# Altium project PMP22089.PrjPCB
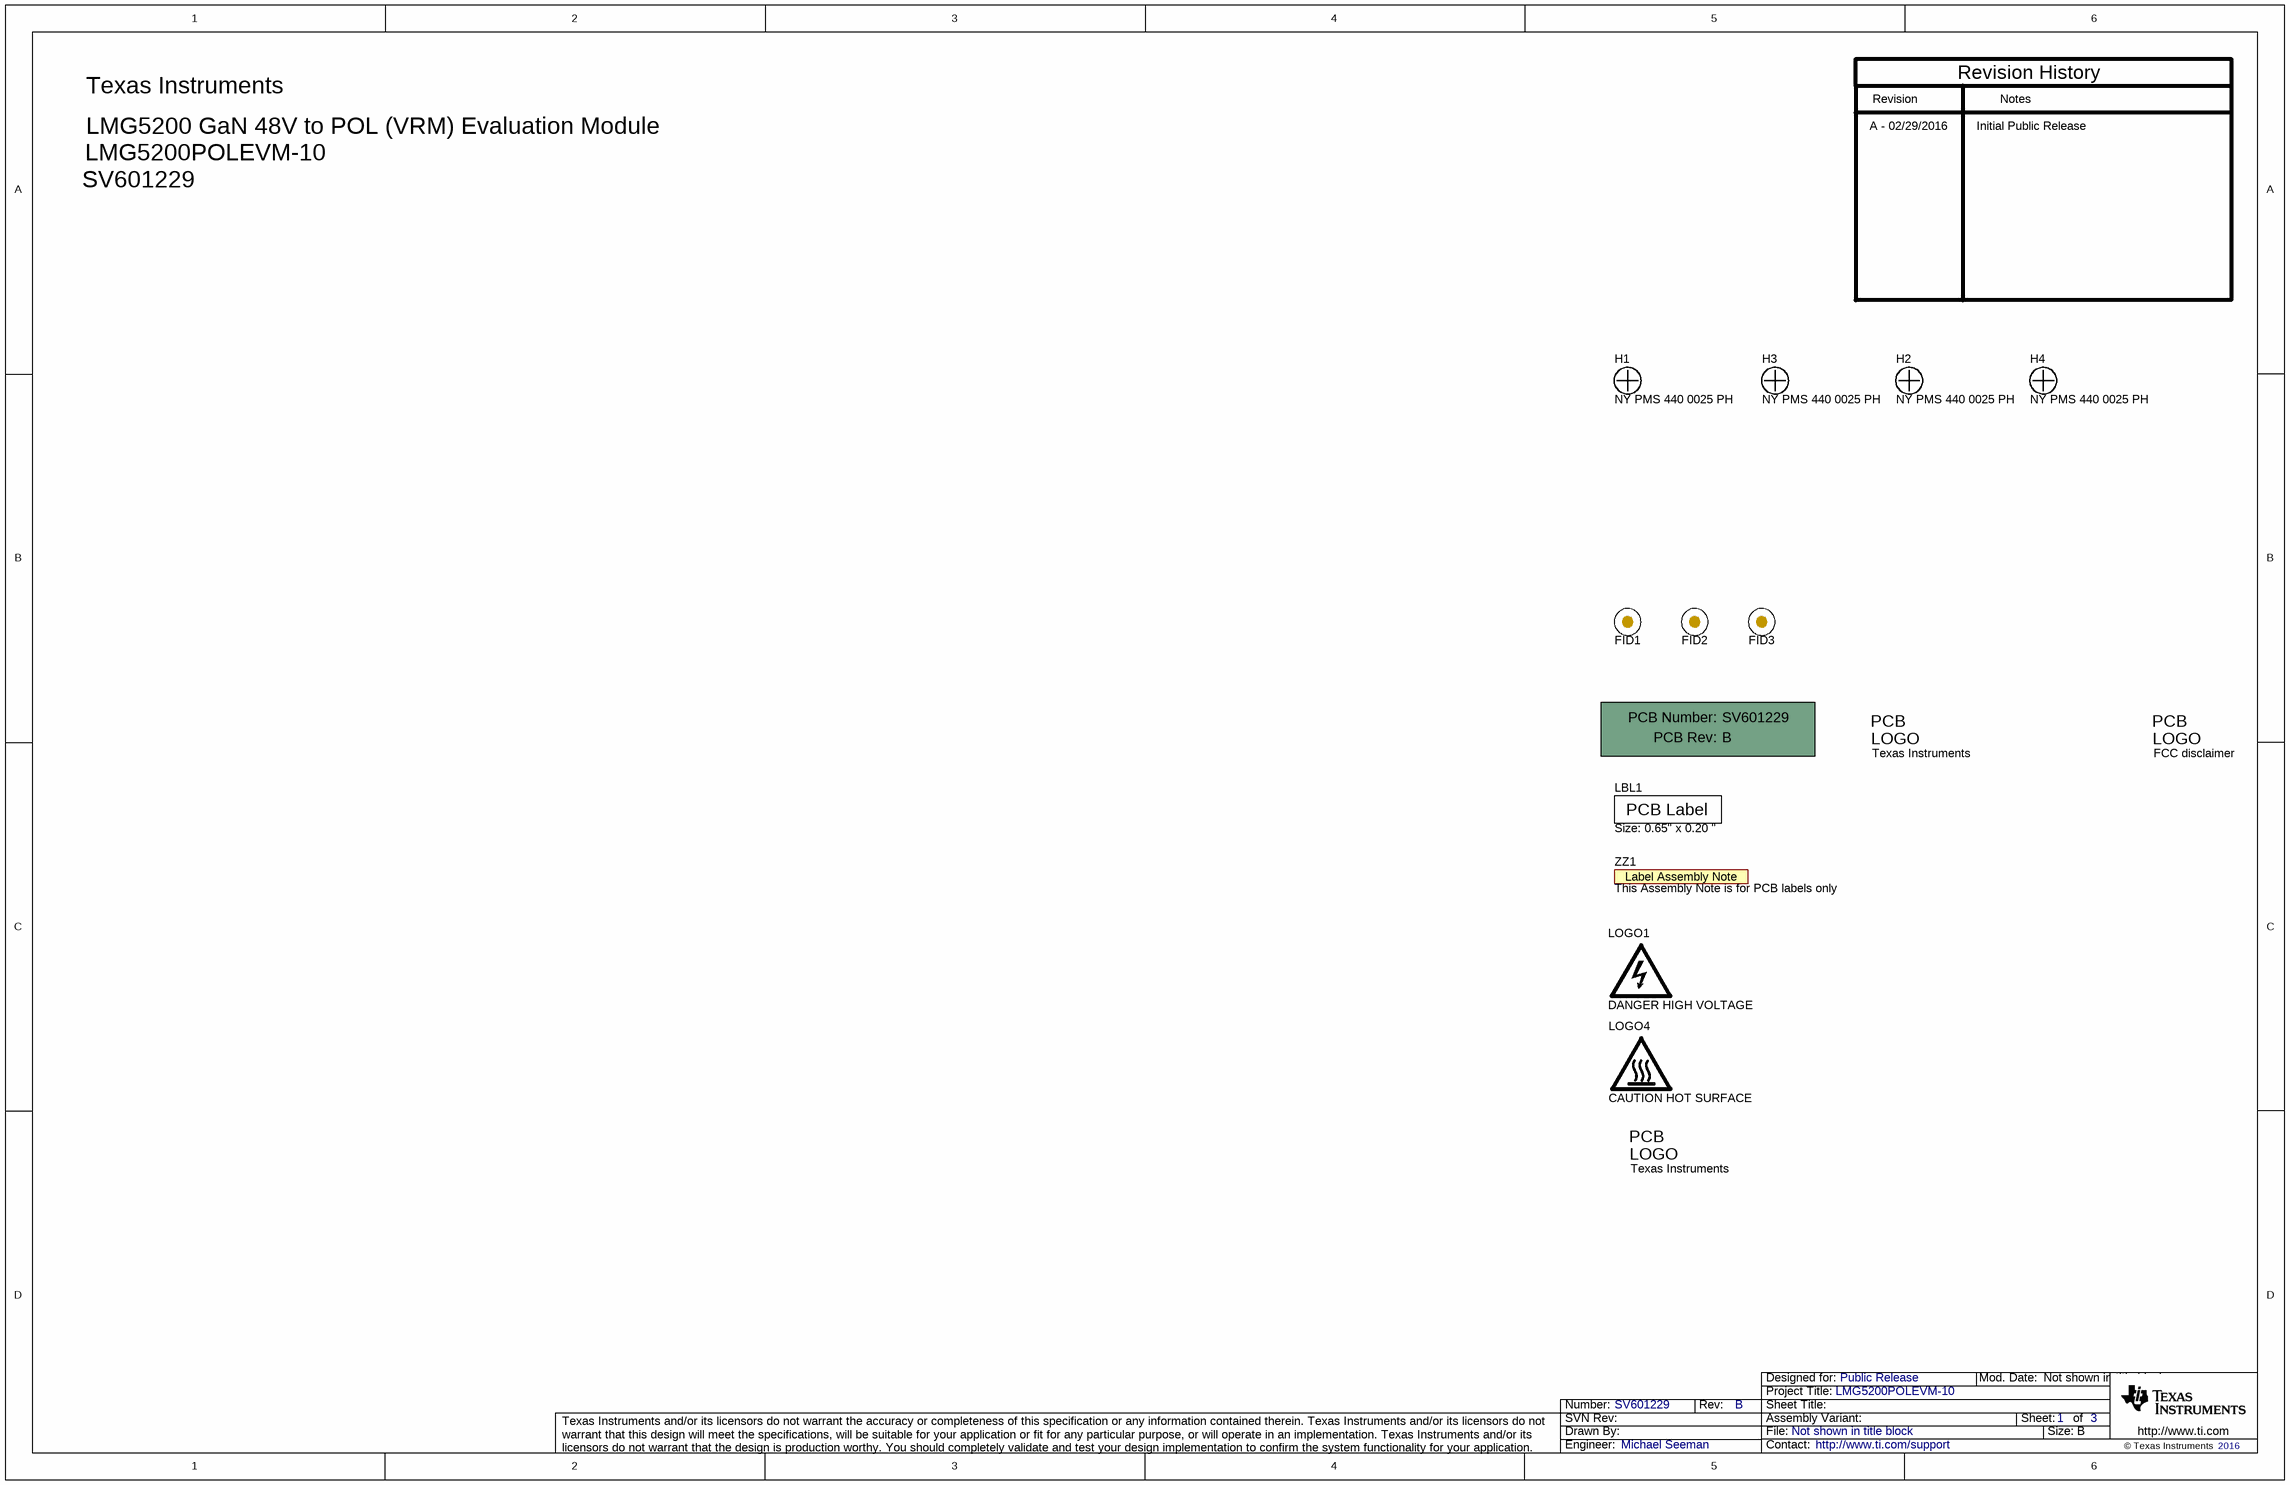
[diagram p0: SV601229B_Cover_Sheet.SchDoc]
CopyrightYear: 2016; PCB_Layout: a0220741; PCB_Rev: B; PRJ_Customer: Public Release; PRJ_Engineer: Michael Seeman; PRJ_Number: SV601229; PRJ_Title: LMG5200POLEVM-10; SCH_Rev: B; TechSupport: http://www.ti.com/support
3 sheets, 188 parts. Net scope: flat (ports and power ports of the same name join across sheets).
Board file: SV601229B_PCB.PcbDoc
Sheets:
  SV601229B_Cover_Sheet.SchDoc
  SV601229B_Controller.SchDoc
  SV601229B_Power_Stage.SchDoc

## Sheet SV601229B_Cover_Sheet.SchDoc
size 431 x 279 mm; Date: Not shown in title block; ApprovedBy: Not shown in title block; CheckedBy: Not shown in title block; Author: Not shown in title block; CompanyName: Not shown in title block; Engineer: Not shown in title block; Organization: Not shown in title block; Address1: Not shown in title block; Address2: Not shown in title block; Address3: Not shown in title block; Address4: Not shown in title block; DocumentNumber: 1; Revision: Use project parameter SCH_Rev; SheetNumber: 1; SheetTotal: 3; PageSetup: Record=PageOptions¦CenterHorizontal=True¦CenterVertical=True¦PrintScale=1.00¦XCorrection=1.00¦YCorrection=1.00¦PrintKind=0¦BorderSize=5000000¦LeftOffset=0¦BottomOffset=0¦Orientation=2¦PaperLength=1000¦PaperWidth=1000¦Scale=100¦PaperSource=15¦PrintQuality=600¦MediaType=1¦DitherType=10¦PaperKind=Letter¦PrintScaleMode=1

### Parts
!PCB1  Printed Circuit Board  (value not drawn)  (mechanical)
FID1  Fiducial  [Fiducial10-20]  (value not drawn)  (mechanical)
FID2  Fiducial  [Fiducial10-20]  (value not drawn)  (mechanical)
FID3  Fiducial  [Fiducial10-20]  (value not drawn)  (mechanical)
H1  NY PMS 440 0025 PH  [NY PMS 440 0025 PH]
H2  NY PMS 440 0025 PH  [NY PMS 440 0025 PH]
H3  NY PMS 440 0025 PH  [NY PMS 440 0025 PH]
H4  NY PMS 440 0025 PH  [NY PMS 440 0025 PH]
LBL1  Size: 0.65" x 0.20 "  [Label_650x200]
LOGO1  DANGER HIGH VOLTAGE  [IEC_HighVoltage_Small]  (no BOM)
Logo2  Texas Instruments  [TI_Stacked_Overlay_Small]  (no BOM)
Logo3  FCC disclaimer  [FCC_disclaimer]  (no BOM)
LOGO4  CAUTION HOT SURFACE  [IEC_HotSurface_Small]  (no BOM)
Logo6  Texas Instruments  [TI_Symbol_Overlay_Small]  (no BOM)
ZZ1  This Assembly Note is for PCB labels only  [AssemblyNoteLabel]  (no BOM)

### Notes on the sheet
- Texas Instruments
- Revision
- Notes
- Revision History
- LMG5200 GaN 48V to POL (VRM) Evaluation Module
- LMG5200POLEVM-10
- A - 02/29/2016
- Initial Public Release
- SV601229

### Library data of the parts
!PCB1 = PCB: Manufacturer: Any; PartNumber: SV601229; SymbolCreator: a0412235
FID1-FID3 = Fiducial: Fiducial mark.  There is nothing to buy or mount.; SymbolCreator: codlsc
H1-H4 = NY PMS 440 0025 PH: Machine Screw, Round, #4-40 x 1/4, Nylon, Philips panhead; Manufacturer: B&F Fastener Supply; CompType: Hardware; SymbolCreator: codlsc; U/M: EA
LBL1 = THT-14-423-10: Thermal Transfer Printable Labels, 0.650" W x 0.200" H - 10,000 per roll; Manufacturer: Brady; SymbolCreator: a0412235; CompType: Label
LOGO1 = IEC_HighVoltage: IEC 61010-1 High Voltage Warning; SymbolCreator: a0412235
Logo2 Logo6 = TI_Logo: Texas Instrument Corporate Signature; SymbolCreator: a0412235
Logo3 = FCC_disclaimer: SymbolCreator: codlsc
LOGO4 = IEC_HotSurface: IEC 61010-1 Hot Surface Warning; SymbolCreator: a0412235
ZZ1 = AssemblyNoteLabel: SymbolCreator: a0412235

## Sheet SV601229B_Controller.SchDoc
size 431 x 279 mm; Date: Not shown in title block; ApprovedBy: Not shown in title block; CheckedBy: Not shown in title block; Author: Not shown in title block; CompanyName: Not shown in title block; Engineer: Not shown in title block; Organization: Not shown in title block; Address1: Not shown in title block; Address2: Not shown in title block; Address3: Not shown in title block; Address4: Not shown in title block; DocumentNumber: 3; Revision: Use project parameter SCH_Rev; SheetNumber: 3; SheetTotal: 3; PageSetup: Record=PageOptions¦CenterHorizontal=True¦CenterVertical=True¦PrintScale=1.00¦XCorrection=1.00¦YCorrection=1.00¦PrintKind=0¦BorderSize=5000000¦LeftOffset=0¦BottomOffset=0¦Orientation=2¦PaperLength=1000¦PaperWidth=1000¦Scale=100¦PaperSource=15¦PrintQuality=600¦MediaType=1¦DitherType=10¦PaperKind=Letter¦PrintScaleMode=1
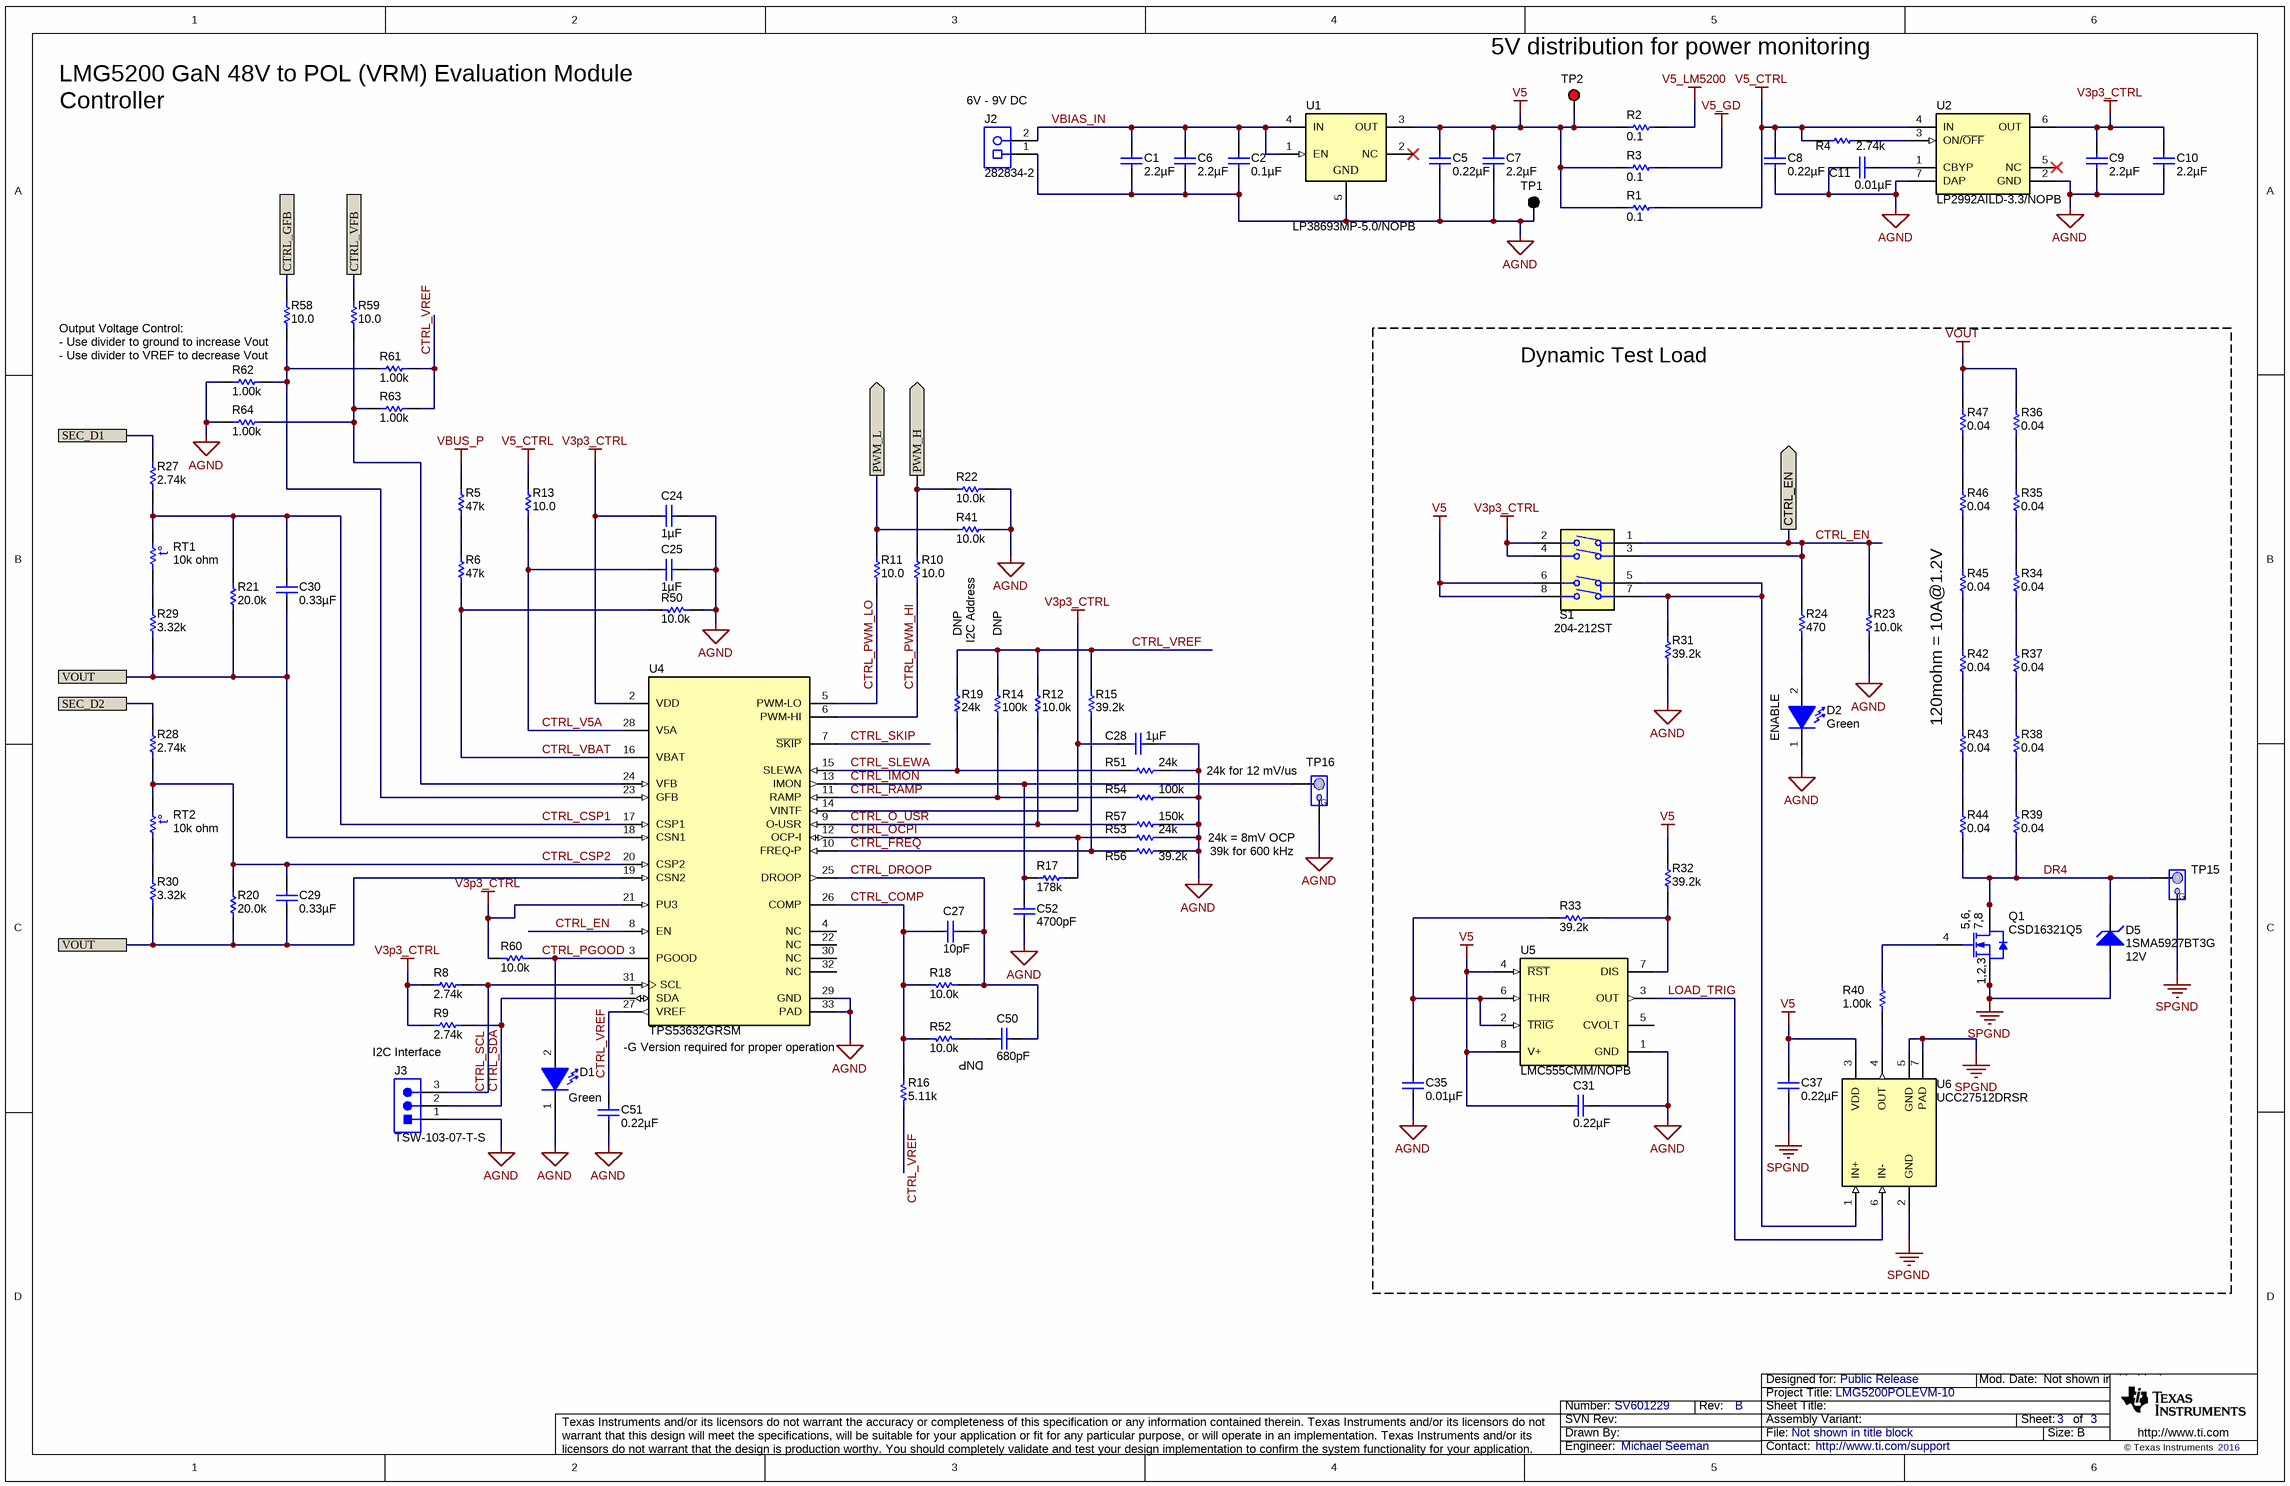
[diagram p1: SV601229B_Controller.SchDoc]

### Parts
C1  ValueDisplayed: 2.2µF  [0805]  (hidden comment: C0805C225K4RACTU)
C2  ValueDisplayed: 0.1µF  [0402]  (hidden comment: C1005X7R1H104K050BB)
C5  ValueDisplayed: 0.22µF  [0402]  (hidden comment: C1005X7R1C224K050BC)
C6  ValueDisplayed: 2.2µF  [0805]  (hidden comment: C0805C225K4RACTU)
C7  ValueDisplayed: 2.2µF  [0805]  (hidden comment: C0805C225K4RACTU)
C8  ValueDisplayed: 0.22µF  [0402]  (hidden comment: C1005X7R1C224K050BC)
C9  ValueDisplayed: 2.2µF  [0805]  (hidden comment: C0805C225K4RACTU)
C10  ValueDisplayed: 2.2µF  [0805]  (hidden comment: C0805C225K4RACTU)
C11  ValueDisplayed: 0.01µF  [0402]  (hidden comment: C1005X7R1C103K050BA)
C24  ValueDisplayed: 1µF  [0402]  (hidden comment: GRM155R61A105KE15D)
C25  ValueDisplayed: 1µF  [0402]  (hidden comment: GRM155R61A105KE15D)
C27  ValueDisplayed: 10pF  [0402]  (hidden comment: GRM1555C1H100JA01D)
C28  ValueDisplayed: 1µF  [0402]  (hidden comment: GRM155R61A105KE15D)
C29  ValueDisplayed: 0.33µF  [0603]  (hidden comment: GRM188R71C334KA01D)
C30  ValueDisplayed: 0.33µF  [0603]  (hidden comment: GRM188R71C334KA01D)
C31  ValueDisplayed: 0.22µF  [0603]  (hidden comment: C0603C224K4RACTU)
C35  ValueDisplayed: 0.01µF  [0402]  (hidden comment: C1005X7R1C103K050BA)
C37  ValueDisplayed: 0.22µF  [0603]  (hidden comment: C0603C224K4RACTU)
C50  ValueDisplayed: 680pF  [0402]  (hidden comment: GRM1555C1E681JA01D)
C51  ValueDisplayed: 0.22µF  [0402]  (hidden comment: C1005X7R1C224K050BC)
C52  ValueDisplayed: 4700pF  [0402]  (hidden comment: GRM155R71C472KA01D)
D1  value Green  [WL-SMCW_GREEN]  (hidden comment: 150060GS75000)
D2  value Green  [WL-SMCW_GREEN]  (hidden comment: 150060GS75000)
D5  1SMA5927BT3G  value 12V  [SMA]
J2  282834-2  [TEC_282834-2]
J3  TSW-103-07-T-S  [Samtec_TSW-103-07-T-S]
Q1  CSD16321Q5  [TRANS_NexFET_Q5]
R1  ValueDisplayed: 0.1  [0402]  (hidden comment: ERJ-2BSFR10X)
R2  ValueDisplayed: 0.1  [0402]  (hidden comment: ERJ-2BSFR10X)
R3  ValueDisplayed: 0.1  [0402]  (hidden comment: ERJ-2BSFR10X)
R4  ValueDisplayed: 2.74k  [0402]  (hidden comment: CRCW04022K74FKED)
R5  ValueDisplayed: 47k  [0402]  (hidden comment: CRCW040247K0JNED)
R6  ValueDisplayed: 47k  [0402]  (hidden comment: CRCW040247K0JNED)
R8  ValueDisplayed: 2.74k  [0402]  (hidden comment: CRCW04022K74FKED)
R9  ValueDisplayed: 2.74k  [0402]  (hidden comment: CRCW04022K74FKED)
R10  ValueDisplayed: 10.0  [0402]  (hidden comment: CRCW040210R0FKED)
R11  ValueDisplayed: 10.0  [0402]  (hidden comment: CRCW040210R0FKED)
R12  ValueDisplayed: 10.0k  [0402]  (hidden comment: CRCW040210K0FKED)
R13  ValueDisplayed: 10.0  [0402]  (hidden comment: CRCW040210R0FKED)
R14  ValueDisplayed: 100k  [0402]  (hidden comment: CRCW0402100KFKED)
R15  ValueDisplayed: 39.2k  [0402]  (hidden comment: CRCW040239K2FKED)
R16  ValueDisplayed: 5.11k  [0402]  (hidden comment: CRCW04025K11FKED)
R17  ValueDisplayed: 178k  [0402]  (hidden comment: CRCW0402178KFKED)
R18  ValueDisplayed: 10.0k  [0402]  (hidden comment: CRCW040210K0FKED)
R19  ValueDisplayed: 24k  [0402]  (hidden comment: CRCW040224K0JNED)
R20  ValueDisplayed: 20.0k  [0402]  (hidden comment: CRCW040220K0FKED)
R21  ValueDisplayed: 20.0k  [0402]  (hidden comment: CRCW040220K0FKED)
R22  ValueDisplayed: 10.0k  [0402]  (hidden comment: CRCW040210K0FKED)
R23  ValueDisplayed: 10.0k  [0402]  (hidden comment: CRCW040210K0FKED)
R24  ValueDisplayed: 470  [0402]  (hidden comment: CRCW0402470RJNED)
R27  ValueDisplayed: 2.74k  [0402]  (hidden comment: CRCW04022K74FKED)
R28  ValueDisplayed: 2.74k  [0402]  (hidden comment: CRCW04022K74FKED)
R29  ValueDisplayed: 3.32k  [0402]  (hidden comment: CRCW04023K32FKED)
R30  ValueDisplayed: 3.32k  [0402]  (hidden comment: CRCW04023K32FKED)
R31  ValueDisplayed: 39.2k  [0402]  (hidden comment: CRCW040239K2FKED)
R32  ValueDisplayed: 39.2k  [0402]  (hidden comment: CRCW040239K2FKED)
R33  ValueDisplayed: 39.2k  [0402]  (hidden comment: CRCW040239K2FKED)
R34  ValueDisplayed: 0.04  [2512]  (hidden comment: CRA2512-FZ-R040ELF)
R35  ValueDisplayed: 0.04  [2512]  (hidden comment: CRA2512-FZ-R040ELF)
R36  ValueDisplayed: 0.04  [2512]  (hidden comment: CRA2512-FZ-R040ELF)
R37  ValueDisplayed: 0.04  [2512]  (hidden comment: CRA2512-FZ-R040ELF)
R38  ValueDisplayed: 0.04  [2512]  (hidden comment: CRA2512-FZ-R040ELF)
R39  ValueDisplayed: 0.04  [2512]  (hidden comment: CRA2512-FZ-R040ELF)
R40  ValueDisplayed: 1.00k  [0402]  (hidden comment: CRCW04021K00FKED)
R41  ValueDisplayed: 10.0k  [0402]  (hidden comment: CRCW040210K0FKED)
R42  ValueDisplayed: 0.04  [2512]  (hidden comment: CRA2512-FZ-R040ELF)
R43  ValueDisplayed: 0.04  [2512]  (hidden comment: CRA2512-FZ-R040ELF)
R44  ValueDisplayed: 0.04  [2512]  (hidden comment: CRA2512-FZ-R040ELF)
R45  ValueDisplayed: 0.04  [2512]  (hidden comment: CRA2512-FZ-R040ELF)
R46  ValueDisplayed: 0.04  [2512]  (hidden comment: CRA2512-FZ-R040ELF)
R47  ValueDisplayed: 0.04  [2512]  (hidden comment: CRA2512-FZ-R040ELF)
R50  ValueDisplayed: 10.0k  [0402]  (hidden comment: CRCW040210K0FKED)
R51  ValueDisplayed: 24k  [0402]  (hidden comment: CRCW040224K0JNED)
R52  ValueDisplayed: 10.0k  [0402]  (hidden comment: CRCW040210K0FKED)
R53  ValueDisplayed: 24k  [0402]  (hidden comment: CRCW040224K0JNED)
R54  ValueDisplayed: 100k  [0402]  (hidden comment: CRCW0402100KFKED)
R56  ValueDisplayed: 39.2k  [0402]  (hidden comment: CRCW040239K2FKED)
R57  ValueDisplayed: 150k  [0603]  (hidden comment: CRCW0603150KFKEA)
R58  ValueDisplayed: 10.0  [0402]  (hidden comment: CRCW040210R0FKED)
R59  ValueDisplayed: 10.0  [0402]  (hidden comment: CRCW040210R0FKED)
R60  ValueDisplayed: 10.0k  [0402]  (hidden comment: CRCW040210K0FKED)
R61  ValueDisplayed: 1.00k  [0402]  (hidden comment: CRCW04021K00FKED)
R62  ValueDisplayed: 1.00k  [0402]  (hidden comment: CRCW04021K00FKED)
R63  ValueDisplayed: 1.00k  [0402]  (hidden comment: CRCW04021K00FKED)
R64  ValueDisplayed: 1.00k  [0402]  (hidden comment: CRCW04021K00FKED)
RT1  value 10k ohm  [0402]  (hidden comment: NCP15XH103J03RC)
RT2  value 10k ohm  [0402]  (hidden comment: NCP15XH103J03RC)
S1  204-212ST  [SW_204-212]
TP1  5011  [Keystone5011]  (value not drawn)
TP2  5010  [Keystone5010]  (value not drawn)
TP15  TP_PIGTAIL  [TP_PIGTAIL]  (value not drawn)  (no BOM)
TP16  TP_PIGTAIL  [TP_PIGTAIL]  (value not drawn)  (no BOM)
U1  LP38693MP-5.0/NOPB  [MP05A_N]
U2  LP2992AILD-3.3/NOPB  [LDE06A]
U4  TPS53632GRSM  [RSM0032B_NV]
U5  LMC555CMM/NOPB  [MUA08A_N]
U6  UCC27512DRSR  [DRS0006A]

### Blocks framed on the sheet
Dynamic Test Load: C31 C35 C37 D2 D5 Q1 R23 R24 R31-R40 R42-R47 S1 TP15 U5 U6

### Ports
CTRL_EN (out), CTRL_GFB, CTRL_VFB, PWM_H (out), PWM_L (out), SEC_D1, SEC_D2, VOUT

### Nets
AGND: C1.2 C2.2 C5.1 C6.2 C7.2 C8.1 C9.2 C10.2 C11.2 C24.1 C25.2 C28.1 C31.2 C35.2 C51.2 C52.1 D1.1(K) D2.1(K) J2.1 J3.1 R22.2 R23.1 R31.1 R41.2 R50.2 R51.2 R53.2 R54.2 R56.2 R57.1 R62.2 R64.2 TP1.1 TP16.2 U1.5(GND) U2.2(GND) U2.7(DAP) U4.29(GND) U4.33(PAD) U5.1(GND)
SPGND: C37.2 D5.2(A) Q1.1(S) Q1.2(S) Q1.3(S) TP15.2 U6.2(GND) U6.5(GND) U6.7(PAD)
V3p3_CTRL: C9.1 C10.1 C24.2 C28.2 R8.2 R9.2 R60.2 S1.2 S1.4 U2.6(OUT) U4.2(VDD) U4.14(VINTF) U4.21(PU3)
V5: C5.2 C7.1 C31.1 C37.1 R1.1 R2.1 R3.1 R32.1 S1.6 S1.8 TP2.1 U1.3(OUT) U5.4(~{RST}) U5.8(V+) U6.3(VDD)
V5_CTRL: C8.2 R1.2 R4.2 R13.2 U2.4(IN)
V5_GD: R3.2
V5_LM5200: R2.2
VBUS_P: R5.2
VOUT: C29.2 C30.2 R20.1 R21.1 R29.1 R30.1 R36.2 R47.2 U4.18(CSN1) U4.19(CSN2) ; port VOUT
CTRL_COMP: C27.1 R16.1 R18.2 R52.2 U4.26(COMP)
CTRL_CSP1: C30.1 R21.2 R27.1 RT1.2 U4.17(CSP1)
CTRL_CSP2: C29.1 R20.2 R28.1 RT2.2 U4.20(CSP2)
CTRL_DROOP: C27.2 C50.2 R18.1 U4.25(DROOP)
CTRL_EN: R23.2 R24.2 S1.1 S1.3 U4.8(EN) ; port CTRL_EN
CTRL_FREQ: R15.1 R56.1 U4.10(FREQ-P)
CTRL_GFB: R58.2 ; port CTRL_GFB
CTRL_IMON: C52.2 R17.2 TP16.1 U4.13(IMON)
CTRL_O_USR: R12.2 R57.2 U4.9(O-USR)
CTRL_OCPI: R17.1 R53.1 U4.12(OCP-I)
CTRL_PGOOD: D1.2(A) R60.1 U4.3(PGOOD)
CTRL_PWM_HI: R10.2 U4.6(PWM-HI)
CTRL_PWM_LO: R11.2 U4.5(PWM-LO)
CTRL_RAMP: R14.2 R54.1 U4.11(RAMP)
CTRL_SCL: J3.3 R8.1 U4.31(SCL)
CTRL_SDA: J3.2 R9.1 U4.1(SDA)
CTRL_SKIP: U4.7(~{SKIP})
CTRL_SLEWA: R19.1 R51.1 U4.15(SLEWA)
CTRL_V5A: C25.1 R13.1 U4.28(V5A)
CTRL_VBAT: R6.1 R50.1 U4.16(VBAT)
CTRL_VFB: R59.2 ; port CTRL_VFB
CTRL_VREF: C51.1 R12.1 R14.1 R15.2 R16.2 R19.2 R61.1 R63.1 U4.27(VREF)
DR4: D5.1(K) Q1.5(D) Q1.6(D) Q1.7(D) Q1.8(D) Q1.9(D) R39.1 R44.1 TP15.1
LOAD_TRIG: U5.3(OUT) U6.6(IN-)
PWM_H: R10.1 R22.1 ; port PWM_H
PWM_L: R11.1 R41.1 ; port PWM_L
SEC_D1: R27.2 ; port SEC_D1
SEC_D2: R28.2 ; port SEC_D2
VBIAS_IN: C1.1 C2.1 C6.1 J2.2 U1.1(EN) U1.4(IN)
NetC11_1: C11.1 U2.1(CBYP)
NetC35_1: C35.1 R33.1 U5.2(~{TRIG}) U5.6(THR)
NetC50_1: C50.1 R52.1
NetD2_2: D2.2(A) R24.1
NetQ1_4: Q1.4(G) R40.2
NetR4_1: R4.1 U2.3(ON/~{OFF})
NetR5_1: R5.1 R6.2
NetR29_2: R29.2 RT1.1
NetR30_2: R30.2 RT2.1
NetR31_2: R31.2 S1.5 S1.7 U6.1(IN+)
NetR32_2: R32.2 R33.2 U5.7(DIS)
NetR34_1: R34.1 R37.2
NetR34_2: R34.2 R35.1
NetR35_2: R35.2 R36.1
NetR37_1: R37.1 R38.2
NetR38_1: R38.1 R39.2
NetR40_1: R40.1 U6.4(OUT)
NetR42_1: R42.1 R43.2
NetR42_2: R42.2 R45.1
NetR43_1: R43.1 R44.2
NetR45_2: R45.2 R46.1
NetR46_2: R46.2 R47.1
NetR58_1: R58.1 R61.2 R62.1 U4.23(GFB)
NetR59_1: R59.1 R63.2 R64.1 U4.24(VFB)

Not connected (* = marked no-connect by the designer): U1 2(NC)*; U2 5(NC)*; U4 4(NC) 22(NC) 30(NC) 32(NC); U5 5(CVOLT)

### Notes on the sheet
- LMG5200 GaN 48V to POL (VRM) Evaluation Module
- Controller
- (near J2) 6V - 9V DC
- (near TP2) 5V distribution for power monitoring
- Output Voltage Control:
- (near R58) - Use divider to ground to increase Vout
- - Use divider to VREF to decrease Vout
- DNP
- I2C Address
- 120mohm = 10A@1.2V
- (near TP16) 24k for 12 mV/us
- (near D2) ENABLE
- (near TP16) 24k = 8mV OCP
- 39k for 600 kHz
- (near U4) -G Version required for proper operation
- I2C Interface

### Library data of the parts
C1 C6 C7 C9 C10 = C0805C225K4RACTU: CAP, CERM, 2.2 µF, 16 V, +/- 10%, X7R, 0805; Manufacturer: Kemet; Polarized: N; CompType: Capacitor; Value: 2.2uF; U/M: EA; Cap_F: 0.0000022; Tolerance_%: 10; ESR_ohm: 0.008; Value1: 0.008 ohm; VDC_V: 16; Value2: 16V; IRMS_A: 15.55; TaMin_C: -55; TaMax_C: 125
C2 = C1005X7R1H104K050BB: CAP, CERM, 0.1 µF, 50 V, +/- 10%, X7R, 0402; Manufacturer: TDK; Polarized: N; CompType: Capacitor; Value: 0.1uF; U/M: EA; Cap_F: 0.0000001; Tolerance_%: 10; ESR_ohm: 0.039064; Value1: 0.039064 ohm; VDC_V: 50; Value2: 50V; IRMS_A: 0.814669; TaMin_C: -55; TaMax_C: 125; AEC Category: Q200
C5 C8 C51 = C1005X7R1C224K050BC: CAP, CERM, 0.22 µF, 16 V, +/- 10%, X7R, 0402; Manufacturer: TDK; Polarized: N; CompType: Capacitor; Value: 0.22uF; U/M: EA; Cap_F: 0.00000022; Tolerance_%: 10; Value1: Unknown; VDC_V: 16; Value2: 16V; TaMin_C: -55; TaMax_C: 125
C11 C35 = C1005X7R1C103K050BA: CAP, CERM, 0.01 µF, 16 V, +/- 10%, X7R, 0402; Manufacturer: TDK; Polarized: N; CompType: Capacitor; Value: 0.01uF; U/M: EA; Cap_F: 0.00000001; Tolerance_%: 10; ESR_ohm: 0.0623; Value1: 0.0623 ohm; VDC_V: 16; Value2: 16V; TaMin_C: -55; TaMax_C: 125; AEC Category: Q200
C24 C25 C28 = GRM155R61A105KE15D: CAP, CERM, 1uF, 10V, +/-10%, X5R, 0402; Manufacturer: MuRata; Polarized: N; CompType: Capacitor; U/M: EA; Cap_F: 0.000001; Tolerance_%: 10; Value1: Unknown; TaMin_C: -55; TaMax_C: 85
C27 = GRM1555C1H100JA01D: CAP, CERM, 10 pF, 50 V, +/- 5%, C0G/NP0, 0402; Manufacturer: MuRata; Polarized: N; CompType: Capacitor; Value: 10pF; U/M: EA; Cap_F: 0.00000000001; Tolerance_%: 5; Value1: Unknown; VDC_V: 50; Value2: 50V; TaMin_C: -55; TaMax_C: 125
C29 C30 = GRM188R71C334KA01D: CAP, CERM, 0.33 µF, 16 V, +/- 10%, X7R, 0603; Manufacturer: MuRata; Polarized: N; CompType: Capacitor; Value: 0.33uF; U/M: EA; Cap_F: 0.00000033; Tolerance_%: 10; Value1: Unknown; VDC_V: 16; Value2: 16V; TaMin_C: -55; TaMax_C: 125
C31 C37 = C0603C224K4RACTU: CAP, CERM, 0.22 µF, 16 V, +/- 10%, X7R, 0603; Manufacturer: Kemet; Polarized: N; CompType: Capacitor; Value: 0.22uF; U/M: EA; Cap_F: 0.00000022; Tolerance_%: 10; Value1: Unknown; VDC_V: 16; Value2: 16V; TaMin_C: -55; TaMax_C: 125
C50 = GRM1555C1E681JA01D: CAP, CERM, 680 pF, 25 V, +/- 5%, C0G/NP0, 0402; Manufacturer: MuRata; Polarized: N; CompType: Capacitor; Value: 680pF; U/M: EA; Cap_F: 0.00000000068; Tolerance_%: 5; Value1: Unknown; VDC_V: 25; Value2: 25V; TaMin_C: -55; TaMax_C: 125
C52 = GRM155R71C472KA01D: CAP, CERM, 4700 pF, 16 V, +/- 10%, X7R, 0402; Manufacturer: MuRata; Polarized: N; CompType: Capacitor; Value: 4700pF; U/M: EA; Cap_F: 0.0000000047; Tolerance_%: 10; Value1: Unknown; VDC_V: 16; Value2: 16V; TaMin_C: -55; TaMax_C: 125; AEC Category: Q200
D1 D2 = 150060GS75000: LED, Green, SMD; Manufacturer: Wurth Elektronik eiSos; Type: InGaN; Vf_V: 3.2; Value2: 3.2V; Io_A: 0.02; Tjmax_C: 85; Value1: W; Angle: 140; U/M: EA
D5 = 1SMA5927BT3G: Diode, Zener, 12 V, 1.5 W, SMA; Manufacturer: ON Semiconductor; SymbolCreator: a0412235; U/M: EA; Power_W: 1.5; Vz_V: 12; Value1: 1.5W; RJA_CperW: 250
J2 = 282834-2: Terminal Block, 2x1, 2.54mm, TH; Manufacturer: TE Connectivity; SymbolCreator: a0412235; U/M: EA
J3 = TSW-103-07-T-S: Header, 2.54 mm, 3x1, Tin, TH; Manufacturer: Samtec; SymbolCreator: a0799628; U/M: EA
Q1 = CSD16321Q5: MOSFET, N-CH, 25 V, 100 A, SON 5x6mm; Manufacturer: Texas Instruments; Alternate Manufacturer: None; U/M: EA; ChType: N; Value: 25V; VdsMax_V: 25; Value1: 0.0021 ohm; Rdson45_ohm: 0.0021; Value2: 14 nC; QgTyp_nC: 14; Vgs_V: 10; IdsMax_A: 100; AEC Category: Q101
R1-R3 = ERJ-2BSFR10X: RES, 0.1, 1%, 0.125 W, 0402; Manufacturer: Panasonic; CompType: Resistor; Value: 0.1; Value_Code: R100; Tolerance_%: 1; Power_W: 0.125; Value2: 0.125W; TempCo: 300 ppm/C; EIA_Code: E96; U/M: EA
R4 R8 R9 R27 R28 = CRCW04022K74FKED: RES, 2.74 k, 1%, 0.063 W, 0402; Manufacturer: Vishay-Dale; CompType: Resistor; Value: 2.74k; Res_ohm: 2740; Value_Code: 2k74; Tolerance_%: 1; Power_W: 0.063; Value2: 0.063W; VDC_V: 50; TempCo: 100 ppm/C; EIA_Code: E96; U/M: EA
R5 R6 = CRCW040247K0JNED: RES, 47 k, 5%, 0.063 W, 0402; Manufacturer: Vishay-Dale; CompType: Resistor; Value: 47k; Res_ohm: 47000; Value_Code: 47k0; Tolerance_%: 5; Power_W: 0.063; Value2: 0.063W; VDC_V: 50; TempCo: 200 ppm/C; EIA_Code: E24; U/M: EA
R10 R11 R13 = CRCW040210R0FKED: RES, 10.0, 1%, 0.063 W, 0402; Manufacturer: Vishay-Dale; CompType: Resistor; Value: 10.0; Res_ohm: 10; Value_Code: 10R0; Tolerance_%: 1; Power_W: 0.063; Value2: 0.063W; VDC_V: 50; TempCo: 100 ppm/C; EIA_Code: E96; U/M: EA
R12 R18 R22 R23 R41 R50 R52 R60 = CRCW040210K0FKED: RES, 10.0 k, 1%, 0.063 W, 0402; Manufacturer: Vishay-Dale; CompType: Resistor; Value: 10.0k; Res_ohm: 10000; Value_Code: 10k0; Tolerance_%: 1; Power_W: 0.063; Value2: 0.063W; VDC_V: 50; TempCo: 100 ppm/C; EIA_Code: E96; U/M: EA
R14 R54 = CRCW0402100KFKED: RES, 100 k, 1%, 0.063 W, 0402; Manufacturer: Vishay-Dale; CompType: Resistor; Value: 100k; Res_ohm: 100000; Tolerance_%: 1; Power_W: 0.063; Value2: 0.063W; VDC_V: 50; TempCo: 100 ppm/C; EIA_Code: E96; U/M: EA
R15 R31-R33 R56 = CRCW040239K2FKED: RES, 39.2 k, 1%, 0.063 W, 0402; Manufacturer: Vishay-Dale; CompType: Resistor; Value: 39.2k; Res_ohm: 39200; Value_Code: 39k2; Tolerance_%: 1; Power_W: 0.063; Value2: 0.063W; VDC_V: 50; TempCo: 100 ppm/C; EIA_Code: E96; U/M: EA
R16 = CRCW04025K11FKED: RES, 5.11 k, 1%, 0.063 W, 0402; Manufacturer: Vishay-Dale; CompType: Resistor; Value: 5.11k; Res_ohm: 5110; Value_Code: 5k11; Tolerance_%: 1; Power_W: 0.063; Value2: 0.063W; VDC_V: 50; TempCo: 100 ppm/C; EIA_Code: E96; U/M: EA
R17 = CRCW0402178KFKED: RES, 178 k, 1%, 0.063 W, 0402; Manufacturer: Vishay-Dale; CompType: Resistor; Value: 178k; Res_ohm: 178000; Tolerance_%: 1; Power_W: 0.063; Value2: 0.063W; VDC_V: 50; TempCo: 100 ppm/C; EIA_Code: E96; U/M: EA
R19 R51 R53 = CRCW040224K0JNED: RES, 24 k, 5%, 0.063 W, 0402; Manufacturer: Vishay-Dale; CompType: Resistor; Value: 24k; Res_ohm: 24000; Value_Code: 24k0; Tolerance_%: 5; Power_W: 0.063; Value2: 0.063W; VDC_V: 50; TempCo: 200 ppm/C; EIA_Code: E24; U/M: EA
R20 R21 = CRCW040220K0FKED: RES, 20.0 k, 1%, 0.063 W, 0402; Manufacturer: Vishay-Dale; CompType: Resistor; Value: 20.0k; Res_ohm: 20000; Value_Code: 20k0; Tolerance_%: 1; Power_W: 0.063; Value2: 0.063W; VDC_V: 50; TempCo: 100 ppm/C; EIA_Code: E96; U/M: EA
R24 = CRCW0402470RJNED: RES, 470, 5%, 0.063 W, 0402; Manufacturer: Vishay-Dale; CompType: Resistor; Value: 470; Value_Code: 470R; Tolerance_%: 5; Power_W: 0.063; Value2: 0.063W; VDC_V: 50; TempCo: 200 ppm/C; EIA_Code: E24; U/M: EA
R29 R30 = CRCW04023K32FKED: RES, 3.32 k, 1%, 0.063 W, 0402; Manufacturer: Vishay-Dale; CompType: Resistor; Value: 3.32k; Res_ohm: 3320; Value_Code: 3k32; Tolerance_%: 1; Power_W: 0.063; Value2: 0.063W; VDC_V: 50; TempCo: 100 ppm/C; EIA_Code: E96; U/M: EA
R34-R39 R42-R47 = CRA2512-FZ-R040ELF: RES, 0.04, 1%, 3 W, 2512; Manufacturer: Bourns; CompType: Resistor; Value: 0.04; Value_Code: R040; Tolerance_%: 1; Power_W: 3; Value2: 3W; VDC_V: 0; TempCo: 75 ppm/C; U/M: EA
R40 R61-R64 = CRCW04021K00FKED: RES, 1.00 k, 1%, 0.063 W, 0402; Manufacturer: Vishay-Dale; CompType: Resistor; Value: 1.00k; Res_ohm: 1000; Value_Code: 1k00; Tolerance_%: 1; Power_W: 0.063; Value2: 0.063W; VDC_V: 50; TempCo: 100 ppm/C; EIA_Code: E96; U/M: EA; AEC Category: Q200
R57 = CRCW0603150KFKEA: RES, 150 k, 1%, 0.1 W, 0603; Manufacturer: Vishay-Dale; CompType: Resistor; Value: 150k; Res_ohm: 150000; Tolerance_%: 1; Power_W: 0.1; Value2: 0.1W; VDC_V: 75; TempCo: 100 ppm/C; EIA_Code: E96; U/M: EA
R58 R59 = CRCW040210R0FKED: RES, 10.0, 1%, 0.063 W, 0402; Manufacturer: Vishay-Dale; CompType: Resistor; Value: 10.0; Res_ohm: 10; Value_Code: 10R0; Tolerance_%: 1; Power_W: 0.063; Value2: 0.063W; VDC_V: 50; TempCo: 100 ppm/C; EIA_Code: E96; U/M: EA; AEC Category: Q200
RT1 RT2 = NCP15XH103J03RC: Thermistor NTC, 10k ohm, 5%, 0402; Manufacturer: MuRata; Tolerance_%: 5; Power_W: 0.1; TaMin_C: -40; TaMax_C: 125; U/M: EA
S1 = 204-212ST: Switch, DPST, 2 Pos, 0.1 A, 50 VDC, SMD; Manufacturer: CTS Electrocomponents; SymbolCreator: Altium; VDC_V: 50; SwitchFunction: Off-On; PositionCount: 2; CurrentRating_mA: 100
TP1 = 5011: Test Point, Multipurpose, Black, TH; Manufacturer: Keystone; CompType: Test Point Loop; U/M: EA
TP2 = 5010: Test Point, Multipurpose, Red, TH; Manufacturer: Keystone; CompType: Test Point Loop; U/M: EA
TP15 TP16 = TP_PIGTAIL: Testpoint PCB footprint for pigtail probe; Manufacturer: Used in BOM report; SymbolVersion: use current date i.e. 2008-05-20; SymbolCreator: Use a-id; CompType: Used in some BOM reports.  Useful for finding later.; U/M: EA, IN, or GM
U1 = LP38693MP-5.0/NOPB: 500mA Low Dropout CMOS Linear Regulators Stable with Ceramic Output Capacitors, 5-pin SOT-223, Pb-Free; Manufacturer: Texas Instruments; PackageTopMarking: XYTT*LJZB; PowerWise: Y; CompType: LDO IC
U2 = LP2992AILD-3.3/NOPB: Micropower 250 mA Low-Noise Ultra Low-Dropout Regulator, 6-pin LLP, Pb-Free; Manufacturer: Texas Instruments; PackageTopMarking: ZXYTT*L014A; PowerWise: N; CompType: LDO IC
U4 = TPS53632GRSM: Half-Bridge D-CAP+TM Controller for 48V GaN DC/DC Converter, RSM0032B; Manufacturer: Texas Instruments; SymbolCreator: Altium; CompType: IC; U/M: EA
U5 = LMC555CMM/NOPB: CMOS Timer, 8-pin Mini SOIC, Pb-Free; Manufacturer: Texas Instruments; PackageTopMarking: ZXTT*ZC5; PowerWise: N; CompType: Analog IC
U6 = UCC27512DRSR: Single-Channel High-Speed Low-Side Gate Driver with 4-A Peak Source and 8-A Peak Sink, DRS0006A; Alternate PartNumber: UCC27512DRST; Manufacturer: Texas Instruments; SymbolCreator: a0411947; CompType: IC; U/M: EA

## Sheet SV601229B_Power_Stage.SchDoc
size 431 x 279 mm; Date: Not shown in title block; ApprovedBy: Not shown in title block; CheckedBy: Not shown in title block; Author: Not shown in title block; CompanyName: Not shown in title block; Engineer: Not shown in title block; Organization: Not shown in title block; Address1: Not shown in title block; Address2: Not shown in title block; Address3: Not shown in title block; Address4: Not shown in title block; DocumentNumber: 2; Revision: Use project parameter SCH_Rev; SheetNumber: 2; SheetTotal: 3; PageSetup: Record=PageOptions¦CenterHorizontal=True¦CenterVertical=True¦PrintScale=1.00¦XCorrection=1.00¦YCorrection=1.00¦PrintKind=0¦BorderSize=5000000¦LeftOffset=0¦BottomOffset=0¦Orientation=2¦PaperLength=1000¦PaperWidth=1000¦Scale=100¦PaperSource=15¦PrintQuality=600¦MediaType=1¦DitherType=10¦PaperKind=Letter¦PrintScaleMode=1
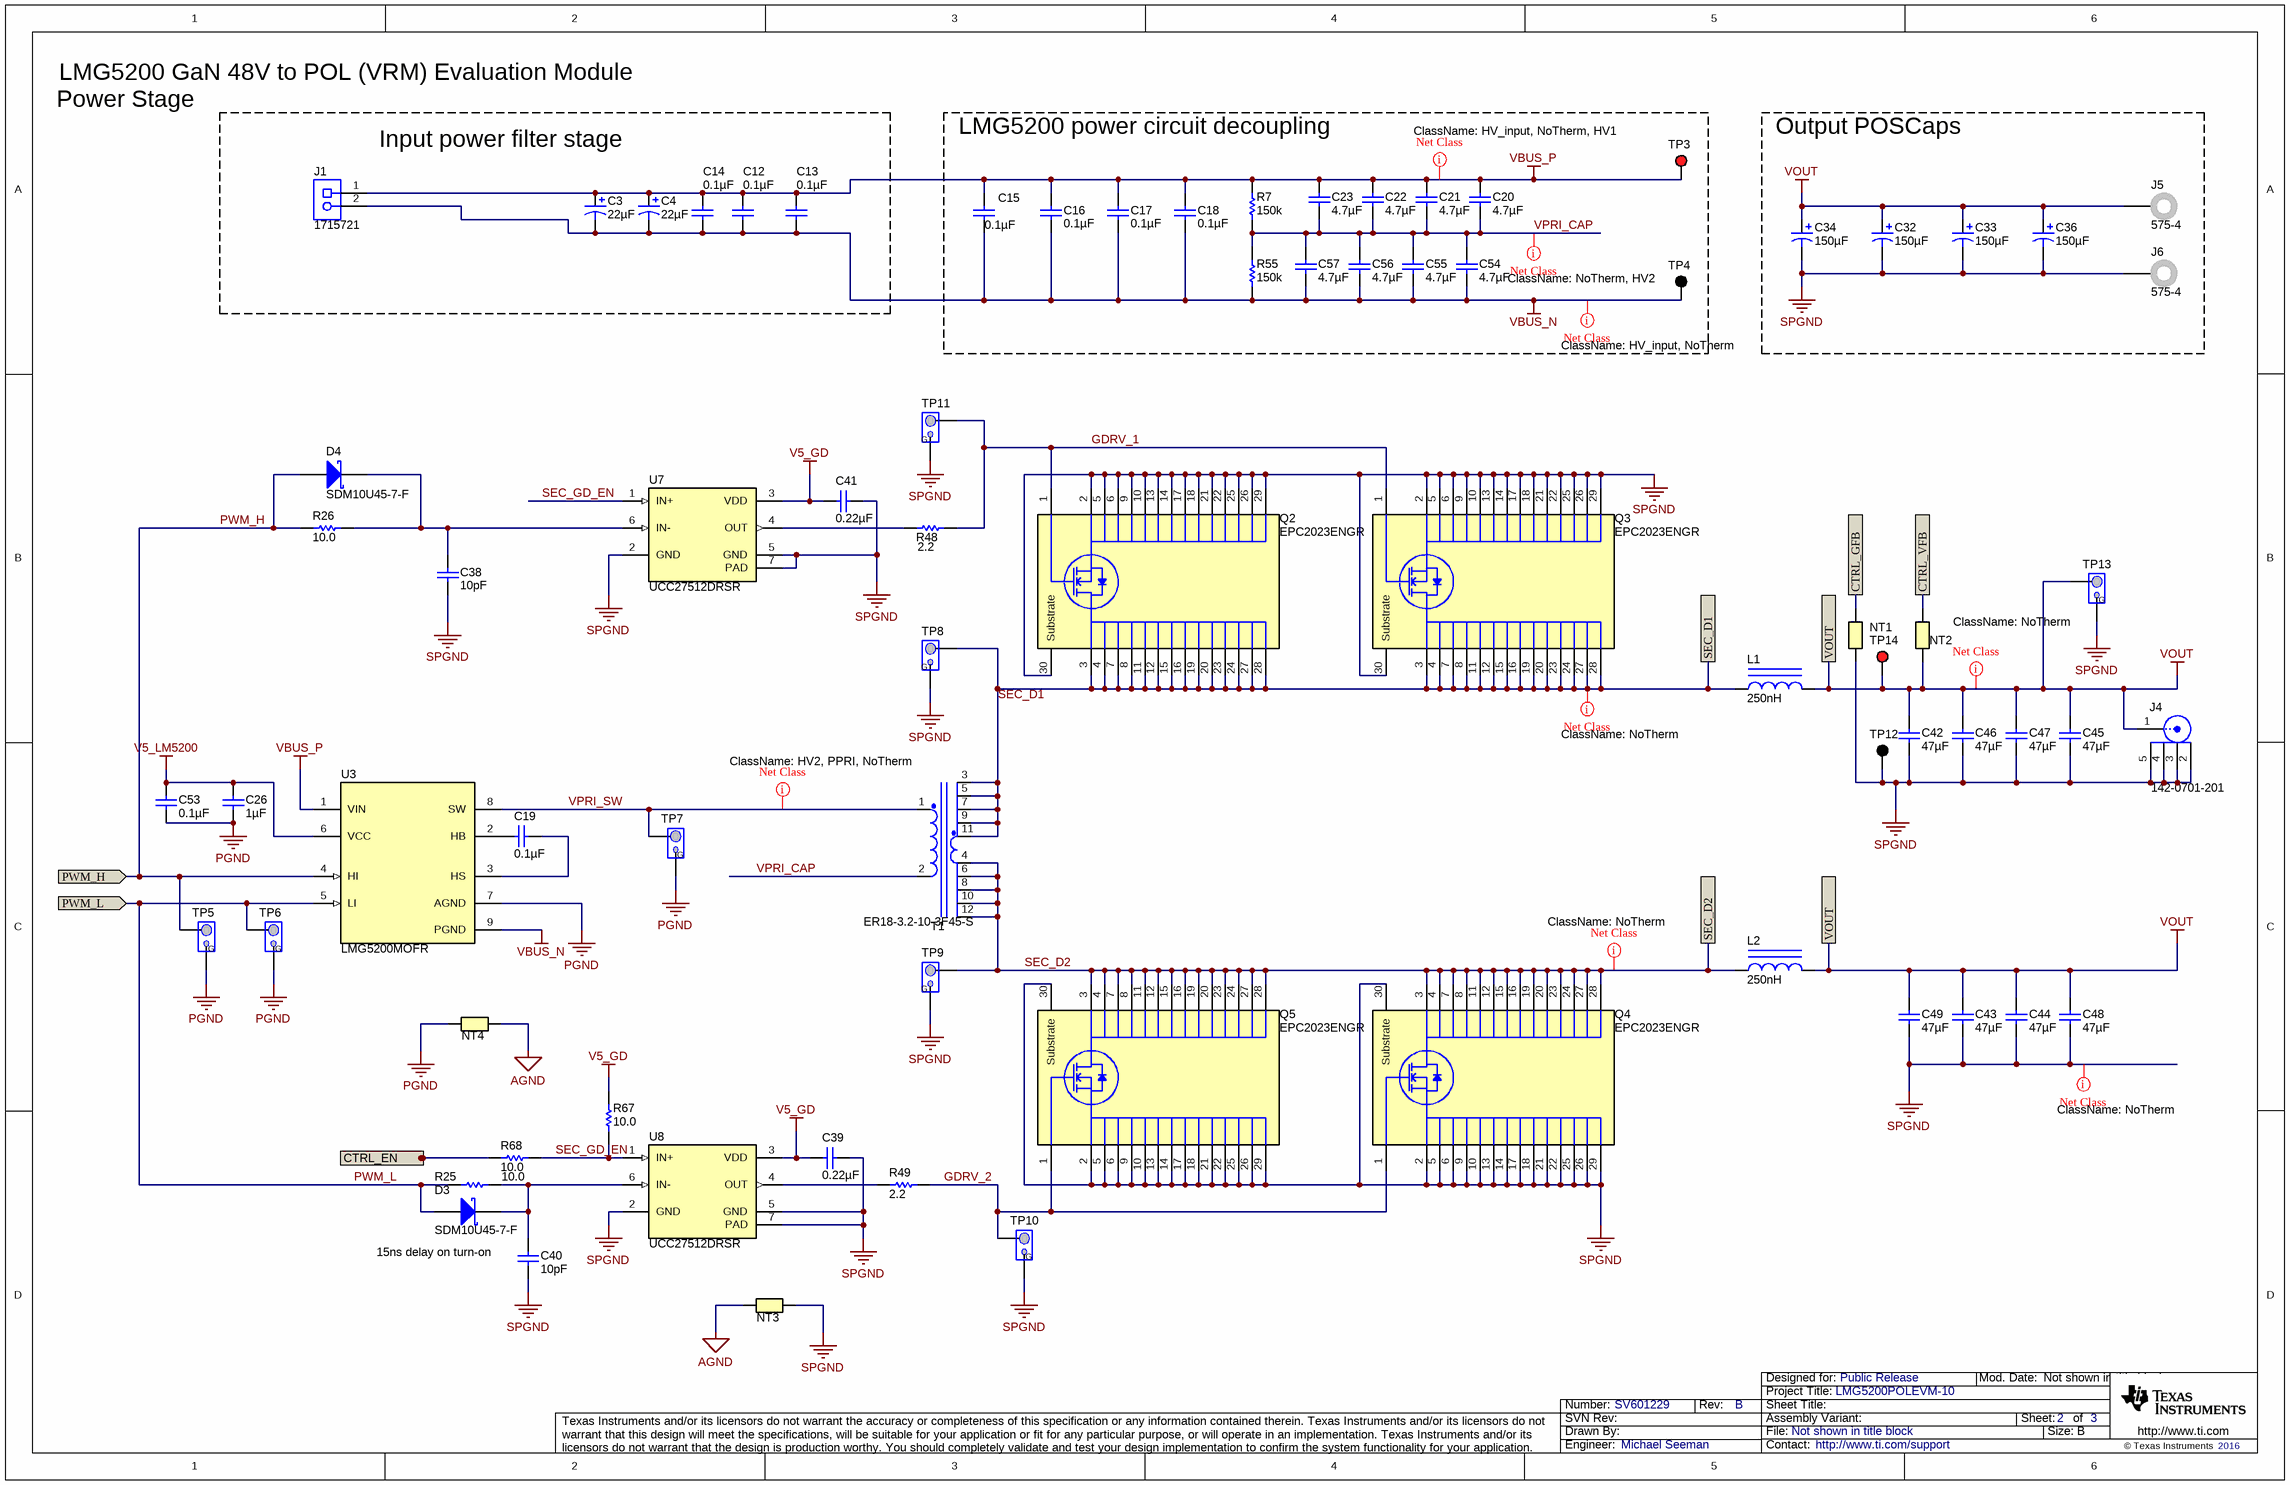
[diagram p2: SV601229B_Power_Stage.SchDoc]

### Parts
C3  ValueDisplayed: 22µF  [CAPSMT_62_HA0]  (hidden comment: EMVA101ADA220MHA0G)
C4  ValueDisplayed: 22µF  [CAPSMT_62_HA0]  (hidden comment: EMVA101ADA220MHA0G)
C12  ValueDisplayed: 0.1µF  [0603S]  (hidden comment: GRM188R72A104KA35J)
C13  ValueDisplayed: 0.1µF  [0603S]  (hidden comment: GRM188R72A104KA35J)
C14  ValueDisplayed: 0.1µF  [0603S]  (hidden comment: GRM188R72A104KA35J)
C15  ValueDisplayed: 0.1µF  [0603S]  (hidden comment: GRM188R72A104KA35J)
C16  ValueDisplayed: 0.1µF  [0603S]  (hidden comment: GRM188R72A104KA35J)
C17  ValueDisplayed: 0.1µF  [0603S]  (hidden comment: GRM188R72A104KA35J)
C18  ValueDisplayed: 0.1µF  [0603S]  (hidden comment: GRM188R72A104KA35J)
C19  ValueDisplayed: 0.1µF  [0402]  (hidden comment: C1005X7R1H104K050BB)
C20  ValueDisplayed: 4.7µF  [0805_HV]  (hidden comment: C2012X5R1H475K125AB)
C21  ValueDisplayed: 4.7µF  [0805_HV]  (hidden comment: C2012X5R1H475K125AB)
C22  ValueDisplayed: 4.7µF  [0805_HV]  (hidden comment: C2012X5R1H475K125AB)
C23  ValueDisplayed: 4.7µF  [0805_HV]  (hidden comment: C2012X5R1H475K125AB)
C26  ValueDisplayed: 1µF  [0402]  (hidden comment: GRM155R61A105KE15D)
C32  ValueDisplayed: 150µF  [3528-21]  (hidden comment: T520B157M006ATE025)
C33  ValueDisplayed: 150µF  [3528-21]  (hidden comment: T520B157M006ATE025)
C34  ValueDisplayed: 150µF  [3528-21]  (hidden comment: T520B157M006ATE025)
C36  ValueDisplayed: 150µF  [3528-21]  (hidden comment: T520B157M006ATE025)
C38  ValueDisplayed: 10pF  [0402]  (hidden comment: GRM1555C1H100JA01D)
C39  ValueDisplayed: 0.22µF  [0402]  (hidden comment: C1005X7R1C224K050BC)
C40  ValueDisplayed: 10pF  [0402]  (hidden comment: GRM1555C1H100JA01D)
C41  ValueDisplayed: 0.22µF  [0402]  (hidden comment: C1005X7R1C224K050BC)
C42  ValueDisplayed: 47µF  [0805L]  (hidden comment: GRM21BR61A476ME15)
C43  ValueDisplayed: 47µF  [0805L]  (hidden comment: GRM21BR61A476ME15)
C44  ValueDisplayed: 47µF  [0805L]  (hidden comment: GRM21BR61A476ME15)
C45  ValueDisplayed: 47µF  [0805L]  (hidden comment: GRM21BR61A476ME15)
C46  ValueDisplayed: 47µF  [0805L]  (hidden comment: GRM21BR61A476ME15)
C47  ValueDisplayed: 47µF  [0805L]  (hidden comment: GRM21BR61A476ME15)
C48  ValueDisplayed: 47µF  [0805L]  (hidden comment: GRM21BR61A476ME15)
C49  ValueDisplayed: 47µF  [0805L]  (hidden comment: GRM21BR61A476ME15)
C53  ValueDisplayed: 0.1µF  [0402]  (hidden comment: C1005X7R1H104K050BB)
C54  ValueDisplayed: 4.7µF  [0805_HV]  (hidden comment: C2012X5R1H475K125AB)
C55  ValueDisplayed: 4.7µF  [0805_HV]  (hidden comment: C2012X5R1H475K125AB)
C56  ValueDisplayed: 4.7µF  [0805_HV]  (hidden comment: C2012X5R1H475K125AB)
C57  ValueDisplayed: 4.7µF  [0805_HV]  (hidden comment: C2012X5R1H475K125AB)
D3  SDM10U45-7-F  [SOD-523]
D4  SDM10U45-7-F  [SOD-523]
J1  1715721  [PhoenixContact_1715721]
J4  142-0701-201  [Johnson_142-0701-20x]
J5  575-4  [Keystone_575-4]
J6  575-4  [Keystone_575-4]
L1  ValueDisplayed: 250nH  [WE-HCM_1070]  (hidden comment: 744308025)
L2  ValueDisplayed: 250nH  [WE-HCM_1070]  (hidden comment: 744308025)
NT1  Net-tie connecting GND polygons under signal traces  [NETTIE_midlayer2]  (value not drawn)  (net tie, no BOM)
NT2  Net-tie connecting GND polygons under signal traces  [NETTIE_midlayer2]  (value not drawn)  (net tie, no BOM)
NT3  Net-tie connecting GND polygons under signal traces  [Net-Tie_50milWide_30milLong]  (value not drawn)  (net tie, no BOM)
NT4  Net-tie connecting GND polygons under signal traces  [Net-Tie_50milWide_30milLong]  (value not drawn)  (net tie, no BOM)
Q2  EPC2023ENGR  [EPC2023]
Q3  EPC2023ENGR  [EPC2023]
Q4  EPC2023ENGR  [EPC2023]
Q5  EPC2023ENGR  [EPC2023]
R7  ValueDisplayed: 150k  [0603]  (hidden comment: CRCW0603150KFKEA)
R25  ValueDisplayed: 10.0  [0402]  (hidden comment: CRCW040210R0FKED)
R26  ValueDisplayed: 10.0  [0402]  (hidden comment: CRCW040210R0FKED)
R48  ValueDisplayed: 2.2  [0603]  (hidden comment: CRCW06032R20JNEA)
R49  ValueDisplayed: 2.2  [0603]  (hidden comment: CRCW06032R20JNEA)
R55  ValueDisplayed: 150k  [0603]  (hidden comment: CRCW0603150KFKEA)
R67  ValueDisplayed: 10.0  [0402]  (hidden comment: CRCW040210R0FKED)
R68  ValueDisplayed: 10.0  [0402]  (hidden comment: CRCW040210R0FKED)
T1  ER18-3.2-10-3F45-S  [ER18_3to1_A]  (net tie)
TP3  5010  [Keystone5010]  (value not drawn)
TP4  5011  [Keystone5011]  (value not drawn)
TP5  TESTPOINT_PIGTAIL  [TP_PIGTAIL]  (value not drawn)  (no BOM)
TP6  TESTPOINT_PIGTAIL  [TP_PIGTAIL]  (value not drawn)  (no BOM)
TP7  TESTPOINT_PIGTAIL  [TP_PIGTAIL]  (value not drawn)  (no BOM)
TP8  TESTPOINT_PIGTAIL  [TP_PIGTAIL]  (value not drawn)  (no BOM)
TP9  TESTPOINT_PIGTAIL  [TP_PIGTAIL]  (value not drawn)  (no BOM)
TP10  TESTPOINT_PIGTAIL  [TP_PIGTAIL]  (value not drawn)  (no BOM)
TP11  TESTPOINT_PIGTAIL  [TP_PIGTAIL]  (value not drawn)  (no BOM)
TP12  5011  [Keystone5011]  (value not drawn)
TP13  TESTPOINT_PIGTAIL  [TP_PIGTAIL]  (value not drawn)  (no BOM)
TP14  5010  [Keystone5010]  (value not drawn)
U3  LMG5200MOFR  [MOF0009A]
U7  UCC27512DRSR  [DRS0006A]
U8  UCC27512DRSR  [DRS0006A]

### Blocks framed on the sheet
Input power filter stage: C3 C4 C12-C14 J1
LMG5200 power circuit decoupling: C15-C18 C20-C23 C54-C57 R7 R55 TP3 TP4
Output POSCaps: C32-C34 C36 J5 J6

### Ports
CTRL_EN (in), CTRL_GFB, CTRL_VFB, PWM_H (in), PWM_L (in), SEC_D1, SEC_D2, VOUT

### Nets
AGND: NT3.1 NT4.2
PGND: C26.2 C53.2 NT4.1 TP5.2 TP6.2 TP7.2 U3.7(AGND)
SPGND: C32.2(-) C33.2(-) C34.2(-) C36.2(-) C38.2 C39.1 C40.2 C41.1 C42.2 C43.2 C44.2 C45.2 C46.2 C47.2 C48.2 C49.2 J4.2 J4.3 J4.4 J4.5 J6.1 NT1.2 NT3.2 Q2.2(S) Q2.5(S) Q2.6(S) Q2.9(S) Q2.10(S) Q2.13(S) Q2.14(S) Q2.17(S) Q2.18(S) Q2.21(S) Q2.22(S) Q2.25(S) Q2.26(S) Q2.29(S) Q2.30(Substrate) Q3.2(S) Q3.5(S) Q3.6(S) Q3.9(S) Q3.10(S) Q3.13(S) Q3.14(S) Q3.17(S) Q3.18(S) Q3.21(S) Q3.22(S) Q3.25(S) Q3.26(S) Q3.29(S) Q3.30(Substrate) Q4.2(S) Q4.5(S) Q4.6(S) Q4.9(S) Q4.10(S) Q4.13(S) Q4.14(S) Q4.17(S) Q4.18(S) Q4.21(S) Q4.22(S) Q4.25(S) Q4.26(S) Q4.29(S) Q4.30(Substrate) Q5.2(S) Q5.5(S) Q5.6(S) Q5.9(S) Q5.10(S) Q5.13(S) Q5.14(S) Q5.17(S) Q5.18(S) Q5.21(S) Q5.22(S) Q5.25(S) Q5.26(S) Q5.29(S) Q5.30(Substrate) TP8.2 TP9.2 TP10.2 TP11.2 TP12.1 TP13.2 U7.2(GND) U7.5(GND) U7.7(PAD) U8.2(GND) U8.5(GND) U8.7(PAD)
V5_GD: C39.2 C41.2 R67.1 U7.3(VDD) U8.3(VDD)
V5_LM5200: C26.1 C53.1 U3.6(VCC)
VBUS_N: C3.2(-) C4.2(-) C12.2 C13.2 C14.2 C15.2 C16.2 C17.2 C18.2 C54.2 C55.2 C56.2 C57.2 J1.2 R55.1 TP4.1 U3.9(PGND)
VBUS_P: C3.1(+) C4.1(+) C12.1 C13.1 C14.1 C15.1 C16.1 C17.1 C18.1 C20.1 C21.1 C22.1 C23.1 J1.1 R7.2 TP3.1 U3.1(VIN)
VOUT: C32.1(+) C33.1(+) C34.1(+) C36.1(+) C42.1 C43.1 C44.1 C45.1 C46.1 C47.1 C48.1 C49.1 J4.1 J5.1 L1.2 L2.2 NT2.2 TP13.1 TP14.1 ; port VOUT
CTRL_EN: R68.1 ; port CTRL_EN
CTRL_GFB: NT1.1 ; port CTRL_GFB
CTRL_VFB: NT2.1 ; port CTRL_VFB
GDRV_1: Q2.1(G) Q3.1(G) R48.2 TP11.1
GDRV_2: Q4.1(G) Q5.1(G) R49.1 TP10.1
PWM_H: D4.2(A) R26.1 TP5.1 U3.4(HI) ; port PWM_H
PWM_L: D3.2(A) R25.1 TP6.1 U3.5(LI) ; port PWM_L
SEC_D1: L1.1 Q2.3(D) Q2.4(D) Q2.7(D) Q2.8(D) Q2.11(D) Q2.12(D) Q2.15(D) Q2.16(D) Q2.19(D) Q2.20(D) Q2.23(D) Q2.24(D) Q2.27(D) Q2.28(D) Q3.3(D) Q3.4(D) Q3.7(D) Q3.8(D) Q3.11(D) Q3.12(D) Q3.15(D) Q3.16(D) Q3.19(D) Q3.20(D) Q3.23(D) Q3.24(D) Q3.27(D) Q3.28(D) T1.3 T1.5 T1.7 T1.9 T1.11 TP8.1 ; port SEC_D1
SEC_D2: L2.1 Q4.3(D) Q4.4(D) Q4.7(D) Q4.8(D) Q4.11(D) Q4.12(D) Q4.15(D) Q4.16(D) Q4.19(D) Q4.20(D) Q4.23(D) Q4.24(D) Q4.27(D) Q4.28(D) Q5.3(D) Q5.4(D) Q5.7(D) Q5.8(D) Q5.11(D) Q5.12(D) Q5.15(D) Q5.16(D) Q5.19(D) Q5.20(D) Q5.23(D) Q5.24(D) Q5.27(D) Q5.28(D) T1.4 T1.6 T1.8 T1.10 T1.12 TP9.1 ; port SEC_D2
SEC_GD_EN: R67.2 R68.2 U7.1(IN+) U8.1(IN+)
VPRI_CAP: C20.2 C21.2 C22.2 C23.2 C54.1 C55.1 C56.1 C57.1 R7.1 R55.2 T1.2
VPRI_SW: T1.1 TP7.1 U3.8(SW)
NetC19_1: C19.1 U3.3(HS)
NetC19_2: C19.2 U3.2(HB)
NetC38_1: C38.1 D4.1(K) R26.2 U7.6(IN-)
NetC40_1: C40.1 D3.1(K) R25.2 U8.6(IN-)
NetR48_1: R48.1 U7.4(OUT)
NetR49_2: R49.2 U8.4(OUT)

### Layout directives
net class HV_input, NoTherm, HV1: VBUS_P
net class HV_input, NoTherm: VBUS_N
net class NoTherm: SEC_D1, SEC_D2, SPGND, VOUT
net class NoTherm, HV2: VPRI_CAP
net class HV2, PPRI, NoTherm: VPRI_SW

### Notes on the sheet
- LMG5200 GaN 48V to POL (VRM) Evaluation Module
- Power Stage
- 15ns delay on turn-on

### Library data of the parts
C3 C4 = EMVA101ADA220MHA0G: CAP, AL, 22 µF, 100 V, +/- 20%,  ohm, SMD; Manufacturer: Chemi-Con; Polarized: Y; CompType: Capacitor; Value: 22uF; U/M: EA; Cap_F: 0.000022; Tolerance_%: 20; Value1: Unknown; VDC_V: 100; Value2: 100V; IRMS_A: 0.09; TaMin_C: -40; TaMax_C: 85; Cap_Case: HA0
C12-C18 = GRM188R72A104KA35J: CAP, CERM, 0.1uF, 100V, +/-10%, X7R, 0603; Manufacturer: MuRata; Polarized: N; CompType: Capacitor; U/M: EA; Cap_F: 0.0000001; Tolerance_%: 10; Value1: Unknown; VDC_V: 100; TaMin_C: -55; TaMax_C: 125; Cap_Case: 0603
C19 C53 = C1005X7R1H104K050BB: as C2 on sheet SV601229B_Controller
C20-C23 C54-C57 = C2012X5R1H475K125AB: CAP, CERM, 4.7uF, 50V, +/-10%, X5R, 0805; Manufacturer: TDK; Polarized: N; CompType: Capacitor; U/M: EA; Cap_F: 0.0000047; Tolerance_%: 10; Value1: Unknown; VDC_V: 50; TaMin_C: -55; TaMax_C: 85; Cap_Case: 0805
C26 = GRM155R61A105KE15D: as C24 on sheet SV601229B_Controller
C32-C34 C36 = T520B157M006ATE025: CAP, TA, 150 µF, 6.3 V, +/- 20%, 0.025 ohm, SMD; Manufacturer: Kemet; Polarized: Y; CompType: Capacitor; Value: 150uF; U/M: EA; Cap_F: 0.00015; Tolerance_%: 20; VDC_V: 6.3; Value2: 6.3V; ESR_ohm: 0.025; IRMS_A: 2.3; TaMin_C: -55; TaMax_C: 105; AEC Category: Q200; AEC Qualified: N
C38 C40 = GRM1555C1H100JA01D: as C27 on sheet SV601229B_Controller
C39 C41 = C1005X7R1C224K050BC: as C5 on sheet SV601229B_Controller
C42-C49 = GRM21BR61A476ME15: CAP, CERM, 47 µF, 10 V, +/- 20%, X5R, 0805; Manufacturer: MuRata; Polarized: N; CompType: Capacitor; Value: 47uF; U/M: EA; Cap_F: 0.000047; Tolerance_%: 20; Value1: Unknown; VDC_V: 10; Value2: 10V; TaMin_C: -55; TaMax_C: 85; Cap_Case: 0805; AEC Category: Q200
D3 D4 = SDM10U45-7-F: Diode, Schottky, 45 V, 0.1 A, SOD-523; Manufacturer: Diodes Inc.; U/M: EA; Vf_V: 0.58; Value: 45V; Value1: 0.1A; Value2: 0.58V; Io_A: 0.1; Vr_V: 45; TJmax_C: 125; AEC Category: Q101
J1 = 1715721: Terminal Block, 5.08 mm, 2x1, TH; Manufacturer: Phoenix Contact; SymbolCreator: a0412235; Pitch_mm: 5.08; Gender: Female; Row_Count: 1; ContactFinish: Tin; Current_A: 17.5; Voltage_V: 400; Cert_CSA: Y; Cert_CULUS: N
J4 = 142-0701-201: Connector, TH, SMA; Manufacturer: Emerson Network Power; SymbolCreator: X0208326; U/M: EA
J5 J6 = 575-4: Standard Banana Jack, Uninsulated, 5.5mm; Manufacturer: Keystone; CompType: Connector; U/M: EA
L1 L2 = 744308025: Inductor, Shielded Drum Core, Ferrite, 250 nH, 27 A, 0.00037 ohm, SMD; Manufacturer: Wurth Elektronik; Value: 250nH; Ind_H: 250.0E-9; Imax_A: 27; Irms: 27A @ 50C rise; Isat: 44A @ 20% inductance drop; Value2: 27A
NT1-NT4 = Net-Tie: Single point connection between nets.; SymbolCreator: codlsc
Q2-Q5 = EPC2023ENGR: MOSFET, N-CH, 30 V, 60 A, 6.05x2.3mm; Manufacturer: EPC; Alternate Manufacturer: None; SymbolCreator: Altium; U/M: EA; ChType: N; Value: 30V; VdsMax_V: 30; Value1: ? ohm; Value2: 20 nC; QgTyp_nC: 20; Vgs_V: 6; IdsMax_A: 60; AEC Category: Q101
R7 R55 = CRCW0603150KFKEA: as R57 on sheet SV601229B_Controller
R25 R26 R67 R68 = CRCW040210R0FKED: as R10 on sheet SV601229B_Controller
R48 R49 = CRCW06032R20JNEA: RES, 2.2, 5%, 0.1 W, 0603; Manufacturer: Vishay-Dale; CompType: Resistor; Value: 2.2; Value_Code: 2R20; Tolerance_%: 5; Power_W: 0.1; Value2: 0.1W; VDC_V: 75; TempCo: 200 ppm/C; EIA_Code: E24; U/M: EA
T1 = T_ER18_5to1_A: Transformer ER18 5:1 turns ratio; Manufacturer: Ferroxcube; SymbolVersion: use current date i.e. 2008-05-20; SymbolCreator: a0220741; U/M: EA
TP3 TP14 = 5010: as TP2 on sheet SV601229B_Controller
TP4 TP12 = 5011: as TP1 on sheet SV601229B_Controller
TP5-TP11 TP13 = TESTPOINT_PIGTAIL: PIGTAIL; Manufacturer: Texas Instruments; SymbolCreator: Altium
U3 = LMG5200MOFR: 80V, 10A GaN Half-Bridge Power Stage, MOF0009A (QFM-9); Alternate PartNumber: LMG5200MOFT; Manufacturer: Texas Instruments; SymbolCreator: Altium; SizeArea_mm2: 48; SizeAreaWB_mm2: 80; SizeX_mm: 6; SizeY_mm: 8; SizeZ_mm: 2; CompType: IC; U/M: EA
U7 U8 = UCC27512DRSR: as U6 on sheet SV601229B_Controller

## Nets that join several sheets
AGND: SV601229B_Controller (40 pins), SV601229B_Power_Stage (NT3.1 NT4.2)
SPGND: SV601229B_Controller (9 pins), SV601229B_Power_Stage (95 pins)
V5_GD: SV601229B_Controller (R3.2), SV601229B_Power_Stage (5 pins)
V5_LM5200: SV601229B_Controller (R2.2), SV601229B_Power_Stage (C26.1 C53.1 U3.6)
VBUS_P: SV601229B_Controller (R5.2), SV601229B_Power_Stage (17 pins)
VOUT: SV601229B_Controller (10 pins), SV601229B_Power_Stage (19 pins)
CTRL_EN: SV601229B_Controller (5 pins), SV601229B_Power_Stage (R68.1)
CTRL_GFB: SV601229B_Controller (R58.2), SV601229B_Power_Stage (NT1.1)
CTRL_VFB: SV601229B_Controller (R59.2), SV601229B_Power_Stage (NT2.1)
PWM_H: SV601229B_Controller (R10.1 R22.1), SV601229B_Power_Stage (D4.2 R26.1 TP5.1 U3.4)
PWM_L: SV601229B_Controller (R11.1 R41.1), SV601229B_Power_Stage (D3.2 R25.1 TP6.1 U3.5)
SEC_D1: SV601229B_Controller (R27.2), SV601229B_Power_Stage (35 pins)
SEC_D2: SV601229B_Controller (R28.2), SV601229B_Power_Stage (35 pins)

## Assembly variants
001: not fitted C50 FID1 FID2 FID3 H1 H2 H3 H4 J5 J6 LOGO1 Logo2 Logo3 LOGO4 Logo5 Logo6 NT1 NT2 NT3 NT4 R14 R19 R52 R61 R62 R63 R64 R68 TP5 TP6 TP7 TP8 TP9 TP10 TP11 TP13 TP15 TP16 ZZ1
